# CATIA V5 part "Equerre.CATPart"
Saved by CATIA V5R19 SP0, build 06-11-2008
Part number: Equerre
Publications: "La", "P", "H", "e"
Bounding box of the stored display mesh (mm): x -50 to 50, y 0 to 150, z 0 to 200
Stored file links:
  G:\EU_thinkMotion\CFAO_2010\MMS_groupe3\MMS_groupe3\A reprendre\evulliez\evulliez\Equerre.CATPart
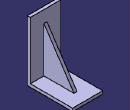
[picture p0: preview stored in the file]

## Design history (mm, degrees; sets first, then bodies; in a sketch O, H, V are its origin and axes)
Parameters
  La = 100 mm
  P = 150 mm
  H = 200 mm
  e = 10 mm
Body1 (main body)
  Sketch1 on yz-plane, origin (0, 0, 0), H (0, 1, 0), V (0, 0, 1)
    line L1 (0, 0) -> (150, 0)
    line L2 (0, 0) -> (0, 200)
    line L3 (0, 200) -> (10, 200)
    line L4 (150, 0) -> (150, 10)
    line L5 (150, 10) -> (10, 10)
    line L6 (10, 200) -> (10, 10)
    length L2 = 200 {= H}
    length L1 = 150 {= P}
    length L3 = 10 {= e}
    length L4 = 10 {= e}
    horizontal: L1 H, L3 H, L5 H
    vertical: L2 V, L4 V, L6 V
  Pad1: profile Sketch1, direction (1, 0, 0), length 50 {= La /2}, mirrored extent
  Sketch2 on yz-plane, origin (0, 0, 0), H (0, 1, 0), V (0, 0, 1)
    line L1 (10, 10) -> (110, 10)
    line L2 (10, 10) -> (10, 160)
    line L3 (10, 160) -> (110, 10)
    distance H L1 = 10 {= e}
    length L1 = 100 {= P -50mm}
    distance V L2 = 10 {= e}
    length L2 = 150 {= H -50mm}
    horizontal: L1 H
    vertical: L2 V
  Pad2: profile Sketch2, direction (1, 0, 0), length 5 {= e /2}, mirrored extent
